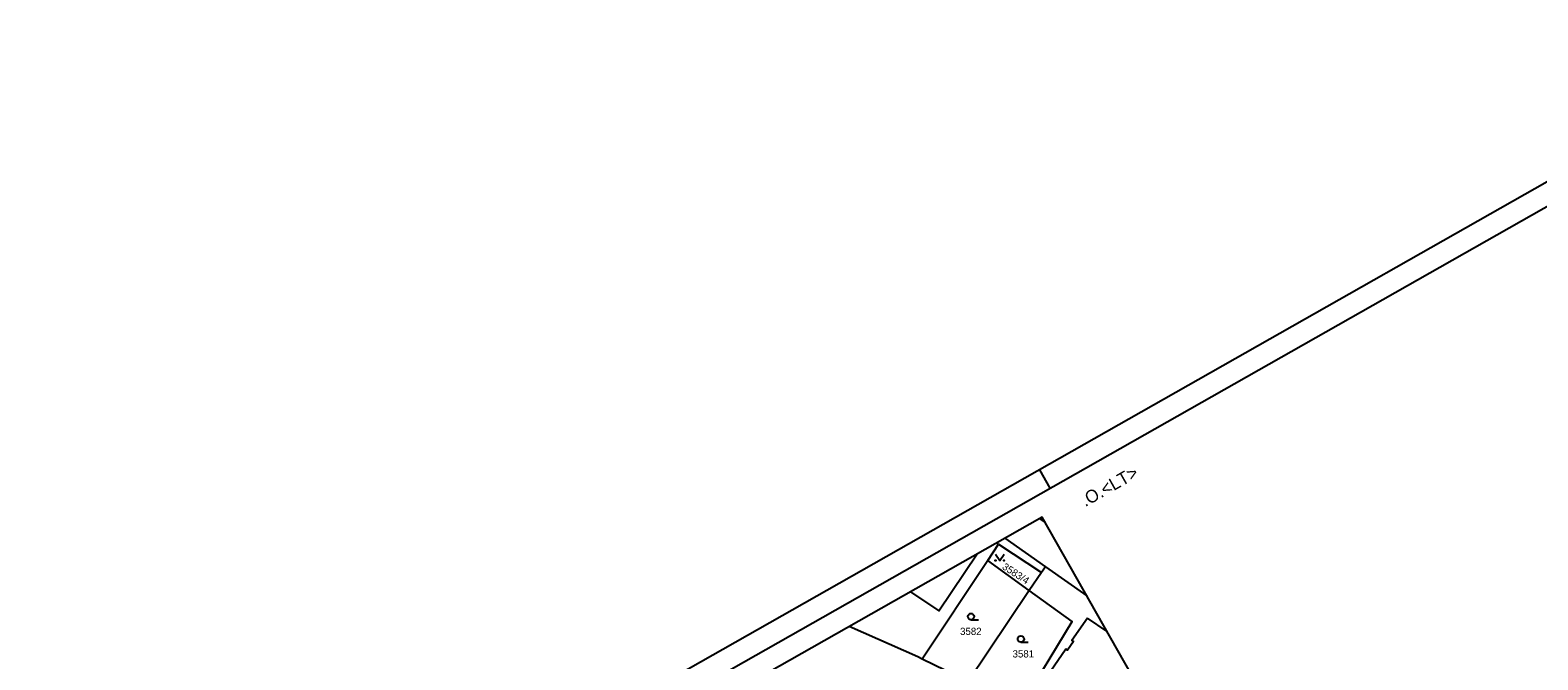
# Model space of a CAD drawing. Extents: x -566165 to -565287, y -1203064 to -1202391.
# Drawn here: x -565854.5 to -565499.2, y -1202539.4 to -1202390.9 of the extents above; entities that cross this region are included whole.
import ezdxf

# ---------------------------------------------------------------- set-up
doc = ezdxf.new("R2010")
doc.units = 0
for name, color, linetype in [('Hranice parcel', 7, 'Continuous'), ('Parcelní čísla', 7, 'Continuous'), ('Vrstva 1', 7, 'Continuous'), ('Značky kultur', 7, 'Continuous')]:
    doc.layers.add(name, color=color, linetype=linetype)

msp = doc.modelspace()

# ---------------------------------------------------------------- linework, layer by layer
at = {"layer": 'Hranice parcel'}
for p, q in [((-565628.8, -1202515.97), (-565626.25, -1202512.14)), ((-565626.25, -1202512.14), (-565626.74, -1202511.81)), ((-565626.25, -1202512.14), (-565616.16, -1202518.81)), ((-565624.8, -1202510.71), (-565615.23, -1202517.43)), ((-565628.8, -1202515.97), (-565644.29, -1202539.18)), ((-565619.01, -1202523.03), (-565628.8, -1202515.97)), ((-565616.16, -1202518.81), (-565619.01, -1202523.03)), ((-565615.23, -1202517.43), (-565616.16, -1202518.81)), ((-565615.23, -1202517.43), (-565605.45, -1202524.29)), ((-565619.01, -1202523.03), (-565633.46, -1202544.45)), ((-565633.46, -1202544.45), (-565644.29, -1202539.18))]:
    msp.add_line(p, q, dxfattribs=at)
for points in [[(-565615.29, -1202506.95), (-565616.58, -1202506.05)], [(-565647.03, -1202523.32), (-565640.37, -1202527.82), (-565631.29, -1202514.39)], [(-565621.07, -1202550.47), (-565608.88, -1202530.33), (-565619.01, -1202523.03)], [(-565605.32, -1202529.54), (-565608.96, -1202534.8), (-565608.59, -1202535.06), (-565610, -1202537.1), (-565610.37, -1202536.85), (-565614.02, -1202542.13), (-565607.67, -1202546.46), (-565608.49, -1202547.77), (-565609.16, -1202548.83)], [(-565600.69, -1202532.69), (-565605.32, -1202529.54)], [(-565644.29, -1202539.18), (-565645.32, -1202538.68), (-565661.47, -1202531.51)]]:
    msp.add_lwpolyline(points, dxfattribs=at)
at = {"layer": 'Vrstva 1'}
msp.add_line((-565614.11, -1202498.9), (-565616.57, -1202494.55), dxfattribs=at)
for points in [[(-566017.99, -1203063.73), (-565287.38, -1202649.25), (-565433.92, -1202390.94), (-566164.53, -1202805.42)], [(-565294.2, -1202647.37), (-566016.11, -1203056.92), (-566157.72, -1202807.3), (-565435.81, -1202397.75)], [(-566014.23, -1203050.11), (-565479.31, -1202746.65), (-565615.99, -1202505.72), (-566150.91, -1202809.18)]]:
    msp.add_lwpolyline(points, close=True, dxfattribs=at)
at = {"layer": 'Značky kultur'}
for p, q in [((-565632.76, -1202529.93), (-565631.01, -1202529.93)), ((-565621, -1202535.22), (-565619.25, -1202535.22))]:
    msp.add_line(p, q, dxfattribs=at)
msp.add_lwpolyline([(-565626.97, -1202514.45), (-565625.97, -1202515.95), (-565624.97, -1202514.45)], dxfattribs=at)
for centre, radius in [((-565626.97, -1202515.95), 0.1), ((-565624.97, -1202515.95), 0.1), ((-565632.76, -1202529.18), 0.75), ((-565621, -1202534.47), 0.75)]:
    msp.add_circle(centre, radius, dxfattribs=at)

# ---------------------------------------------------------------- texts
at = {"layer": 'Parcelní čísla'}
msp.add_text('3583/4', height=1.7, rotation=327, dxfattribs=at).set_placement((-565625.56, -1202517.84))
for s, p in [('3582', (-565635.32, -1202533.51)), ('3581', (-565622.95, -1202538.82))]:
    msp.add_text(s, height=1.7, dxfattribs=at).set_placement(p)
at = {"layer": 'Vrstva 1'}
msp.add_text('.O.<LT>', height=3, rotation=29.5666, dxfattribs=at).set_placement((-565605.82, -1202503.39))

doc.saveas('drawing.dxf')
